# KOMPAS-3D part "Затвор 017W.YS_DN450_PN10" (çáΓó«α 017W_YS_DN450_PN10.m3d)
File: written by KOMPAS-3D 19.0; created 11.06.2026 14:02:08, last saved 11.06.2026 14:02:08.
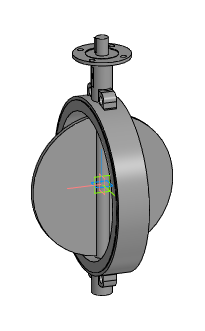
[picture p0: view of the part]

Document properties: Автор: Евгений; Полное имя файла: Z:\3.Личные\kachalov\001_3d для проектировщиков\x.x Тип 017W.Y(S) Затвор дисковый поворотный межфланцевый\_stp_Затвор 017W.YS_DN32-DN1200\Затвор 017W_YS_DN450_PN10.m3d

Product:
- Part/product: Затвор 017W.YS_DN450_PN10

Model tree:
1. Операция без истории:1  (labels: Затвор 017W.YS_DN450_PN10)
